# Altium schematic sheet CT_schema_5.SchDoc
size 284 x 172 mm
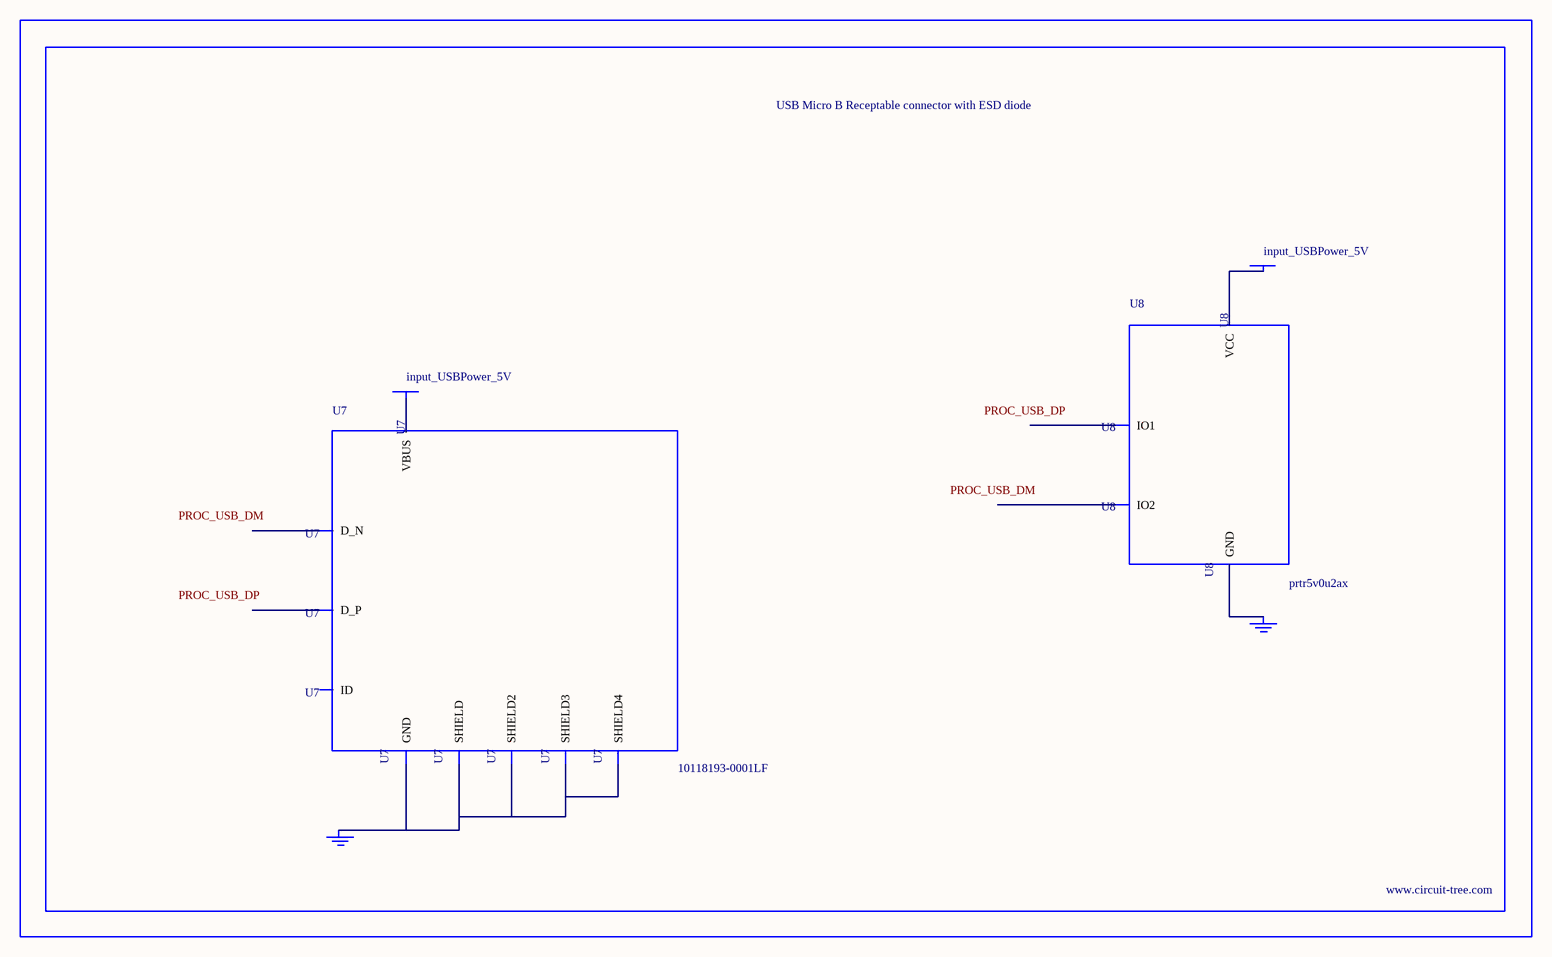
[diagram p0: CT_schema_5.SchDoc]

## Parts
BORDER4  (no value)
GND_INSTANCE_4_0  (no value)
GND_INSTANCE_4_1  (no value)
POWER_INSTANCE_4_0  input_USBPower_5V
POWER_INSTANCE_4_1  input_USBPower_5V
U7  10118193-0001LF  [FCI_10118193-0001LF]
U8  prtr5v0u2ax  [SOT143B]

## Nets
NetGND_INSTANCE_4_0_0: GND_INSTANCE_4_0.0(GND) U7.5(GND) U7.6(SHIELD) U7.7(SHIELD2) U7.8(SHIELD3) U7.9(SHIELD4)
NetGND_INSTANCE_4_1_0: GND_INSTANCE_4_1.0(GND) U8.1(GND)
NetPOWER_INSTANCE_4_0_0: POWER_INSTANCE_4_0.0(PWR) U7.1(VBUS)
NetPOWER_INSTANCE_4_1_0: POWER_INSTANCE_4_1.0(PWR) U8.4(VCC)

Not connected (* = marked no-connect by the designer): U7 2(D_N) 3(D_P) 4(ID); U8 2(IO1) 3(IO2)

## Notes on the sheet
- Labels drawn without touching a wire or pin: PROC_USB_DM, PROC_USB_DP

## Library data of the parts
BORDER4 = BORDER_PAGE4
GND_INSTANCE_4_0 GND_INSTANCE_4_1 = GND
POWER_INSTANCE_4_0 POWER_INSTANCE_4_1 = PWR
